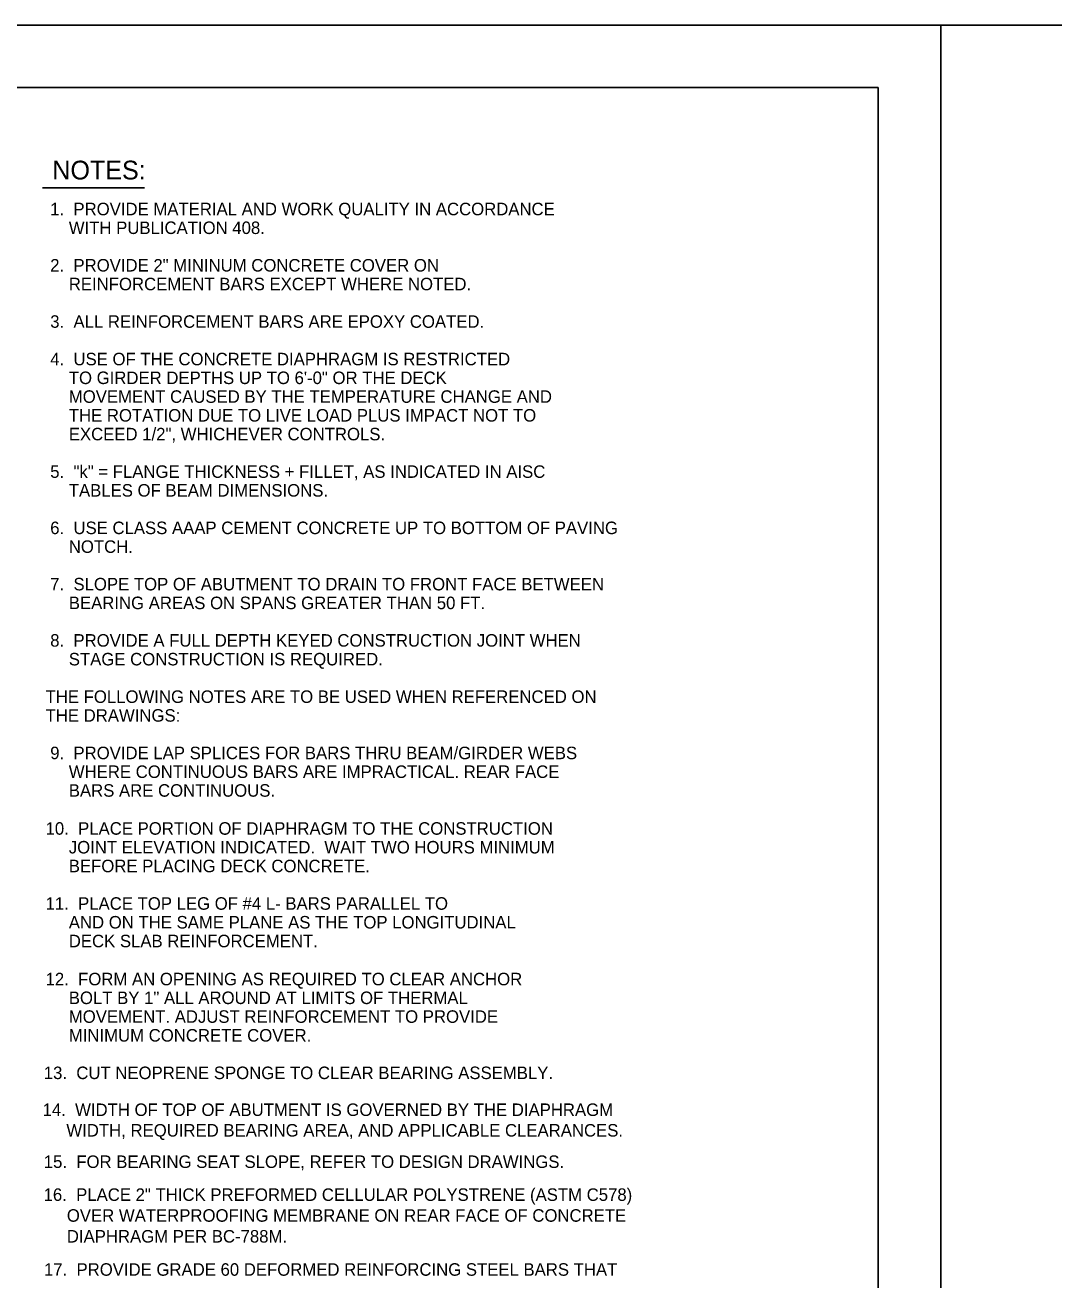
# Model space of a CAD drawing. Extents: x 640009 to 641706, y 298547 to 299735.
# Drawn here: x 640630.8 to 640877.6, y 299434.1 to 299735.2 of the extents above; entities that cross this region are included whole.
import ezdxf

# ---------------------------------------------------------------- set-up
doc = ezdxf.new("R2010")
doc.units = 0
doc.layers.add('1', color=7, linetype='Continuous')
doc.layers.add('PLT-BNDY', color=7, linetype='Continuous')

msp = doc.modelspace()

# ---------------------------------------------------------------- linework, layer by layer
at = {"layer": '1'}
for p, q in [((640049.47, 299720.17), (640835.47, 299720.17)), ((640049.47, 299720.17), (640835.47, 299720.17)), ((640835.47, 299720.17), (640835.47, 299156.17)), ((640835.47, 299720.17), (640835.47, 299156.17)), ((640634.95, 299696.14), (640659.47, 299696.14))]:
    msp.add_line(p, q, dxfattribs=at)
at = {"layer": 'PLT-BNDY'}
for points in [[(640009.47, 299735.17), (640850.47, 299735.17), (640850.47, 299141.17), (640009.47, 299141.17)], [(640850.47, 299735.17), (641691.47, 299735.17), (641691.47, 299141.17), (640850.47, 299141.17)]]:
    msp.add_lwpolyline(points, close=True, dxfattribs=at)

# ---------------------------------------------------------------- texts
at = {"layer": '1'}
for s, height, p in [('NOTES:', 4.5, (640637.32, 299698.14)), (' 1.  PROVIDE MATERIAL AND WORK QUALITY IN ACCORDANCE', 3, (640635.7, 299689.55)), ('     WITH PUBLICATION 408.', 3, (640635.7, 299685.05)), (' 2.  PROVIDE 2" MININUM CONCRETE COVER ON', 3, (640635.7, 299676.05)), ('     REINFORCEMENT BARS EXCEPT WHERE NOTED.', 3, (640635.7, 299671.55)), (' 3.  ALL REINFORCEMENT BARS ARE EPOXY COATED.', 3, (640635.7, 299662.55)), (' 4.  USE OF THE CONCRETE DIAPHRAGM IS RESTRICTED', 3, (640635.7, 299653.55)), ('     TO GIRDER DEPTHS UP TO 6\'-0" OR THE DECK', 3, (640635.7, 299649.05)), ('     MOVEMENT CAUSED BY THE TEMPERATURE CHANGE AND', 3, (640635.7, 299644.55)), ('     THE ROTATION DUE TO LIVE LOAD PLUS IMPACT NOT TO', 3, (640635.7, 299640.05)), ('     EXCEED 1/2", WHICHEVER CONTROLS.', 3, (640635.7, 299635.55)), (' 5.  "k" = FLANGE THICKNESS + FILLET, AS INDICATED IN AISC', 3, (640635.7, 299626.55)), ('     TABLES OF BEAM DIMENSIONS.', 3, (640635.7, 299622.05)), (' 6.  USE CLASS AAAP CEMENT CONCRETE UP TO BOTTOM OF PAVING', 3, (640635.7, 299613.05)), ('     NOTCH.', 3, (640635.7, 299608.55)), (' 7.  SLOPE TOP OF ABUTMENT TO DRAIN TO FRONT FACE BETWEEN', 3, (640635.7, 299599.55)), ('     BEARING AREAS ON SPANS GREATER THAN 50 FT.', 3, (640635.7, 299595.05)), (' 8.  PROVIDE A FULL DEPTH KEYED CONSTRUCTION JOINT WHEN', 3, (640635.7, 299586.05)), ('     STAGE CONSTRUCTION IS REQUIRED.', 3, (640635.7, 299581.55)), ('THE FOLLOWING NOTES ARE TO BE USED WHEN REFERENCED ON', 3, (640635.7, 299572.55)), ('T', 3, (640635.7, 299572.55)), ('THE DRAWINGS:', 3, (640635.7, 299568.05)), (' 9.  PROVIDE LAP SPLICES FOR BARS THRU BEAM/GIRDER WEBS', 3, (640635.7, 299559.05)), ('     WHERE CONTINUOUS BARS ARE IMPRACTICAL. REAR FACE', 3, (640635.7, 299554.55)), ('     BARS ARE CONTINUOUS.', 3, (640635.7, 299550.05)), ('10.  PLACE PORTION OF DIAPHRAGM TO THE CONSTRUCTION', 3, (640635.7, 299540.93)), ('     JOINT ELEVATION INDICATED.  WAIT TWO HOURS MINIMUM', 3, (640635.7, 299536.43)), ('     BEFORE PLACING DECK CONCRETE.', 3, (640635.7, 299531.93)), ('11.  PLACE TOP LEG OF #4 L- BARS PARALLEL TO', 3, (640635.7, 299522.93)), ('     AND ON THE SAME PLANE AS THE TOP LONGITUDINAL', 3, (640635.7, 299518.43)), ('     DECK SLAB REINFORCEMENT.', 3, (640635.7, 299513.93)), ('12.  FORM AN OPENING AS REQUIRED TO CLEAR ANCHOR', 3, (640635.7, 299504.8)), ('     BOLT BY 1" ALL AROUND AT LIMITS OF THERMAL', 3, (640635.7, 299500.3)), ('     MOVEMENT. ADJUST REINFORCEMENT TO PROVIDE', 3, (640635.7, 299495.8)), ('     MINIMUM CONCRETE COVER.', 3, (640635.7, 299491.3)), ('13.  CUT NEOPRENE SPONGE TO CLEAR BEARING ASSEMBLY.', 3, (640635.27, 299482.3)), ('14.  WIDTH OF TOP OF ABUTMENT IS GOVERNED BY THE DIAPHRAGM', 3, (640634.98, 299473.45)), ('     WIDTH, REQUIRED BEARING AREA, AND APPLICABLE CLEARANCES.', 3, (640635.12, 299468.51)), ('15.  FOR BEARING SEAT SLOPE, REFER TO DESIGN DRAWINGS.', 3, (640635.27, 299460.98)), ('16.  PLACE 2" THICK PREFORMED CELLULAR POLYSTRENE (ASTM C578)', 3, (640635.23, 299453.08)), ('     OVER WATERPROOFING MEMBRANE ON REAR FACE OF CONCRETE', 3, (640635.23, 299448.08)), ('     DIAPHRAGM PER BC-788M.', 3, (640635.23, 299443.08)), ('17.  PROVIDE GRADE 60 DEFORMED REINFORCING STEEL BARS THAT ', 3, (640635.32, 299435.12))]:
    msp.add_text(s, height=height, dxfattribs=at).set_placement(p)

doc.saveas('drawing.dxf')
